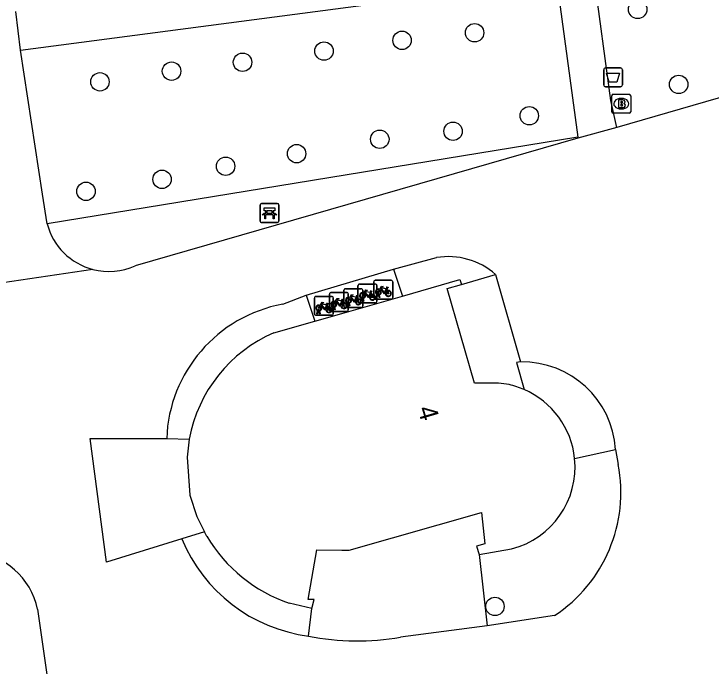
# Model space of a CAD drawing. Extents: x 162157 to 163165, y 378998 to 380775.
# Drawn here: x 162482.61 to 162519.6, y 379969 to 380003.63 of the extents above; entities that cross this region are included whole.
import ezdxf

# ---------------------------------------------------------------- set-up
doc = ezdxf.new("R2010")
doc.units = 0
for name, color, linetype in [('IMGEO_Afvalbak', 7, 'Continuous'), ('IMGEO_Bank', 7, 'Continuous'), ('IMGEO_Boom', 7, 'Continuous'), ('IMGEO_Brandkraan', 7, 'Continuous'), ('IMGEO_Fietsenrek', 7, 'Continuous'), ('IMGEO_Haag', 7, 'Continuous'), ('IMGEO_Loofbos', 7, 'Continuous'), ('IMGEO_Pand', 7, 'Continuous'), ('IMGEO_Pand_nummerreeks', 7, 'Continuous'), ('IMGEO_Parkeervlak_open', 7, 'Continuous'), ('IMGEO_Voetpad_halfverhard', 7, 'Continuous'), ('IMGEO_Voetpad_open', 7, 'Continuous')]:
    doc.layers.add(name, color=color, linetype=linetype)

msp = doc.modelspace()

# ---------------------------------------------------------------- linework, layer by layer
at = {"layer": 'IMGEO_Afvalbak'}
for p, q in [((162513.899, 379999.864), (162513.899, 380000.664)), ((162513.899, 380000.664), (162513.899, 379999.864)), ((162513.999, 380000.764), (162514.789, 380000.764)), ((162514.789, 380000.764), (162513.999, 380000.764)), ((162514.889, 380000.664), (162514.889, 379999.864)), ((162514.889, 379999.864), (162514.889, 380000.664)), ((162514.789, 379999.764), (162513.999, 379999.764)), ((162513.999, 379999.764), (162514.789, 379999.764))]:
    msp.add_line(p, q, dxfattribs=at)
msp.add_lwpolyline([(162514.042, 380000.478), (162514.746, 380000.478), (162514.597, 380000.008), (162514.191, 380000.008), (162514.042, 380000.478)], dxfattribs=at)
for centre, start, end in [((162513.999, 380000.664), 90, 180), ((162513.999, 380000.664), 90, 180), ((162514.789, 380000.664), 0, 90), ((162514.789, 380000.664), 360, 90), ((162513.999, 379999.864), 180, 270), ((162513.999, 379999.864), 180, 270), ((162514.789, 379999.864), 270, 0), ((162514.789, 379999.864), 270, 0)]:
    msp.add_arc(centre, 0.1, start, end, dxfattribs=at)
at = {"layer": 'IMGEO_Bank'}
for p, q in [((162495.666, 379992.631), (162495.666, 379993.472)), ((162495.666, 379993.472), (162495.666, 379992.631)), ((162495.741, 379993.556), (162496.582, 379993.556)), ((162496.582, 379993.556), (162495.741, 379993.556)), ((162496.666, 379993.481), (162496.666, 379992.64)), ((162496.666, 379992.64), (162496.666, 379993.481)), ((162495.975, 379993.062), (162495.975, 379993.168)), ((162496.019, 379993.168), (162496.019, 379993.062)), ((162496.307, 379993.174), (162496.025, 379993.174)), ((162496.025, 379993.056), (162496.307, 379993.056)), ((162496.313, 379993.062), (162496.313, 379993.168)), ((162496.357, 379993.168), (162496.357, 379993.062)), ((162496.363, 379992.954), (162495.97, 379992.954)), ((162496.591, 379992.556), (162495.75, 379992.556)), ((162495.75, 379992.556), (162496.591, 379992.556))]:
    msp.add_line(p, q, dxfattribs=at)
for points in [[(162495.913, 379992.954), (162495.771, 379992.954), (162495.883, 379993.056), (162495.969, 379993.056)], [(162495.969, 379993.174), (162495.883, 379993.174), (162495.883, 379993.335), (162496.446, 379993.335), (162496.446, 379993.174), (162496.363, 379993.174)], [(162496.363, 379993.056), (162496.446, 379993.056), (162496.558, 379992.954), (162496.419, 379992.954)], [(162495.963, 379992.947), (162495.963, 379992.74), (162495.92, 379992.74), (162495.92, 379992.947)], [(162496.413, 379992.947), (162496.413, 379992.74), (162496.369, 379992.74), (162496.369, 379992.947)]]:
    msp.add_lwpolyline(points, dxfattribs=at)
for centre, radius, start, end in [((162495.744, 379993.478), 0.0779, 92.4484, 184.2845), ((162495.744, 379993.478), 0.0779, 92.4484, 184.2845), ((162496.588, 379993.478), 0.0779, 2.4484, 94.2845), ((162496.588, 379993.478), 0.0779, 2.4484, 94.2845), ((162495.968, 379993.167), 0.00671, 2.8957, 87.1043), ((162495.968, 379993.063), 0.00671, 272.8957, 357.1043), ((162496.025, 379993.167), 0.00671, 92.8957, 177.1043), ((162496.025, 379993.063), 0.00671, 182.8957, 267.1043), ((162496.307, 379993.167), 0.00671, 2.8957, 87.1043), ((162496.307, 379993.063), 0.00671, 272.8957, 357.1043), ((162496.364, 379993.167), 0.00671, 92.8957, 177.1043), ((162496.364, 379993.063), 0.00671, 182.8957, 267.1043), ((162495.913, 379992.947), 0.00671, 2.8957, 87.1043), ((162495.97, 379992.947), 0.00671, 92.8957, 177.1043), ((162496.362, 379992.947), 0.00671, 2.8957, 87.1043), ((162496.419, 379992.947), 0.00671, 92.8957, 177.1043), ((162495.744, 379992.634), 0.0779, 182.4484, 274.2845), ((162495.744, 379992.634), 0.0779, 182.4484, 274.2845), ((162496.588, 379992.634), 0.0779, 272.4484, 4.2845), ((162496.588, 379992.634), 0.0779, 272.4484, 4.2845)]:
    msp.add_arc(centre, radius, start, end, dxfattribs=at)
at = {"layer": 'IMGEO_Boom'}
for centre in [(162515.703, 380003.867), (162507.049, 380002.628), (162503.203, 380002.225), (162499.06, 380001.655), (162494.737, 380001.06), (162490.971, 380000.589), (162487.172, 380000.022), (162517.876, 379999.885), (162509.952, 379998.224), (162505.906, 379997.397), (162502.021, 379996.973), (162497.606, 379996.207), (162493.841, 379995.54), (162490.467, 379994.844), (162486.433, 379994.208), (162508.129, 379972.166)]:
    msp.add_circle(centre, 0.489, dxfattribs=at)
at = {"layer": 'IMGEO_Brandkraan'}
for p, q in [((162514.408, 379999.361), (162515.26, 379999.361)), ((162514.333, 379998.435), (162514.333, 379999.287)), ((162514.821, 379999.141), (162514.846, 379999.141)), ((162515.334, 379999.287), (162515.334, 379998.435)), ((162514.844, 379998.581), (162514.819, 379998.581)), ((162515.26, 379998.361), (162514.408, 379998.361))]:
    msp.add_line(p, q, dxfattribs=at)
for points in [[(162514.408, 379999.361), (162515.26, 379999.361)], [(162514.333, 379998.435), (162514.333, 379999.287)], [(162514.681, 379999.061), (162514.681, 379998.661), (162514.894, 379998.661)], [(162514.912, 379999.061), (162514.681, 379999.061)], [(162514.86, 379998.98), (162514.806, 379998.98), (162514.806, 379998.904)], [(162515.334, 379999.287), (162515.334, 379998.435)], [(162514.806, 379998.904), (162514.859, 379998.904)], [(162514.868, 379998.828), (162514.806, 379998.828), (162514.806, 379998.747)], [(162514.806, 379998.747), (162514.868, 379998.747)], [(162515.26, 379998.361), (162514.408, 379998.361)]]:
    msp.add_lwpolyline(points, dxfattribs=at)
for centre, radius, start, end in [((162514.41, 379999.285), 0.0765, 91.552, 178.448), ((162514.41, 379999.285), 0.0765, 91.552, 178.448), ((162515.258, 379999.285), 0.0765, 1.552, 88.448), ((162515.258, 379999.285), 0.0765, 1.552, 88.448), ((162514.861, 379998.942), 0.0379, 267.8285, 90.9355), ((162514.916, 379998.916), 0.145, 59.4692, 91.5367), ((162514.941, 379998.963), 0.0922, 285.5137, 58.1501), ((162514.869, 379998.787), 0.0404, 269.8759, 90.5077), ((162514.9, 379998.912), 0.251, 268.6676, 293.5347), ((162514.946, 379998.771), 0.105, 301.3115, 78.989), ((162514.41, 379998.437), 0.0765, 181.552, 268.448), ((162514.41, 379998.437), 0.0765, 181.552, 268.448), ((162515.258, 379998.437), 0.0765, 271.552, 358.448), ((162515.258, 379998.437), 0.0765, 271.552, 358.448)]:
    msp.add_arc(centre, radius, start, end, dxfattribs=at)
for centre, major_axis, ratio, start_param, end_param in [((162514.82, 379998.861), (-0.387, 0.002), 0.722429, 4.712389, 7.853982), ((162514.845, 379998.861), (-0.39, 0.002), 0.717154, 1.570796, 4.712389)]:
    msp.add_ellipse(centre, major_axis=major_axis, ratio=ratio, start_param=start_param, end_param=end_param, dxfattribs=at)
at = {"layer": 'IMGEO_Fietsenrek'}
for p, q in [((162501.708, 379988.559), (162501.708, 379989.4)), ((162501.708, 379989.4), (162501.708, 379988.559)), ((162501.783, 379989.484), (162502.624, 379989.484)), ((162502.624, 379989.484), (162501.783, 379989.484)), ((162502.708, 379989.409), (162502.708, 379988.568)), ((162502.708, 379988.568), (162502.708, 379989.409)), ((162500.193, 379989.038), (162501.034, 379989.038)), ((162501.034, 379989.038), (162500.193, 379989.038)), ((162500.864, 379988.358), (162500.864, 379989.199)), ((162500.864, 379989.199), (162500.864, 379988.358)), ((162500.939, 379989.283), (162501.78, 379989.283)), ((162501.78, 379989.283), (162500.939, 379989.283)), ((162501.118, 379988.963), (162501.118, 379988.122)), ((162501.118, 379988.122), (162501.118, 379988.963)), ((162501.864, 379989.208), (162501.864, 379988.367)), ((162501.864, 379988.367), (162501.864, 379989.208)), ((162502.395, 379989.033), (162502.431, 379988.938)), ((162498.623, 379988.625), (162499.464, 379988.625)), ((162499.464, 379988.625), (162498.623, 379988.625)), ((162499.348, 379987.909), (162499.348, 379988.75)), ((162499.348, 379988.75), (162499.348, 379987.909)), ((162499.423, 379988.834), (162500.264, 379988.834)), ((162500.264, 379988.834), (162499.423, 379988.834)), ((162500.118, 379988.113), (162500.118, 379988.954)), ((162500.118, 379988.954), (162500.118, 379988.113)), ((162500.348, 379988.759), (162500.348, 379987.918)), ((162500.348, 379987.918), (162500.348, 379988.759)), ((162501.551, 379988.832), (162501.587, 379988.737)), ((162501.835, 379988.568), (162501.874, 379988.728)), ((162501.904, 379988.716), (162501.869, 379988.568)), ((162501.946, 379988.74), (162501.945, 379988.744)), ((162501.987, 379988.568), (162501.953, 379988.71)), ((162501.977, 379988.751), (162501.978, 379988.744)), ((162501.985, 379988.714), (162502.02, 379988.568)), ((162498.548, 379987.7), (162498.548, 379988.541)), ((162498.548, 379988.541), (162498.548, 379987.7)), ((162499.548, 379988.55), (162499.548, 379987.709)), ((162499.548, 379987.709), (162499.548, 379988.55)), ((162500.035, 379988.383), (162500.071, 379988.288)), ((162500.245, 379988.122), (162500.284, 379988.282)), ((162500.314, 379988.27), (162500.279, 379988.122)), ((162500.356, 379988.294), (162500.355, 379988.298)), ((162500.397, 379988.122), (162500.363, 379988.264)), ((162500.387, 379988.305), (162500.388, 379988.298)), ((162500.395, 379988.268), (162500.43, 379988.122)), ((162500.805, 379988.587), (162500.841, 379988.492)), ((162501.789, 379988.283), (162500.948, 379988.283)), ((162500.948, 379988.283), (162501.789, 379988.283)), ((162500.991, 379988.367), (162501.03, 379988.527)), ((162501.025, 379988.367), (162500.991, 379988.367)), ((162501.06, 379988.515), (162501.025, 379988.367)), ((162501.102, 379988.539), (162501.101, 379988.543)), ((162501.143, 379988.367), (162501.109, 379988.509)), ((162501.133, 379988.55), (162501.134, 379988.543)), ((162501.141, 379988.513), (162501.176, 379988.367)), ((162501.176, 379988.367), (162501.143, 379988.367)), ((162502.633, 379988.484), (162501.792, 379988.484)), ((162501.792, 379988.484), (162502.633, 379988.484)), ((162501.869, 379988.568), (162501.835, 379988.568)), ((162502.02, 379988.568), (162501.987, 379988.568)), ((162498.675, 379987.709), (162498.714, 379987.869)), ((162498.744, 379987.857), (162498.709, 379987.709)), ((162498.786, 379987.881), (162498.785, 379987.885)), ((162498.817, 379987.892), (162498.818, 379987.885)), ((162498.825, 379987.855), (162498.86, 379987.709)), ((162499.235, 379988.174), (162499.271, 379988.079)), ((162499.475, 379987.918), (162499.514, 379988.078)), ((162499.509, 379987.918), (162499.475, 379987.918)), ((162499.544, 379988.066), (162499.509, 379987.918)), ((162499.586, 379988.09), (162499.585, 379988.094)), ((162499.627, 379987.918), (162499.593, 379988.06)), ((162499.617, 379988.101), (162499.618, 379988.094)), ((162499.625, 379988.064), (162499.66, 379987.918)), ((162499.66, 379987.918), (162499.627, 379987.918)), ((162501.043, 379988.038), (162500.202, 379988.038)), ((162500.202, 379988.038), (162501.043, 379988.038)), ((162500.279, 379988.122), (162500.245, 379988.122)), ((162500.43, 379988.122), (162500.397, 379988.122)), ((162499.473, 379987.625), (162498.632, 379987.625)), ((162498.632, 379987.625), (162499.473, 379987.625)), ((162498.709, 379987.709), (162498.675, 379987.709)), ((162498.827, 379987.709), (162498.793, 379987.851)), ((162498.86, 379987.709), (162498.827, 379987.709)), ((162500.273, 379987.834), (162499.432, 379987.834)), ((162499.432, 379987.834), (162500.273, 379987.834))]:
    msp.add_line(p, q, dxfattribs=at)
for points in [[(162501.177, 379988.809), (162501.272, 379988.973), (162501.358, 379988.959), (162501.36, 379988.95), (162501.304, 379988.939), (162501.277, 379988.894), (162501.533, 379988.853)], [(162502.042, 379988.958), (162501.99, 379988.868), (162501.95, 379988.843), (162501.951, 379988.89), (162502.006, 379988.984)], [(162502.021, 379989.01), (162502.116, 379989.174), (162502.202, 379989.16), (162502.204, 379989.151), (162502.148, 379989.14), (162502.121, 379989.095), (162502.377, 379989.054)], [(162502.317, 379988.766), (162502.267, 379988.766), (162502.076, 379989.017), (162502.057, 379988.985)], [(162502.364, 379989.029), (162502.107, 379989.07), (162502.09, 379989.041), (162502.257, 379988.821), (162502.364, 379989.029)], [(162502.412, 379988.931), (162502.382, 379989.008), (162502.273, 379988.79), (162502.316, 379988.79)], [(162502.377, 379989.054), (162502.402, 379989.103), (162502.396, 379989.107), (162502.373, 379989.111), (162502.361, 379989.118), (162502.36, 379989.121), (162502.362, 379989.126), (162502.457, 379989.111), (162502.459, 379989.101), (162502.449, 379989.088), (162502.437, 379989.082), (162502.423, 379989.088), (162502.395, 379989.033)], [(162500.431, 379988.564), (162500.526, 379988.728), (162500.612, 379988.714), (162500.614, 379988.705), (162500.558, 379988.694), (162500.531, 379988.649), (162500.787, 379988.608)], [(162500.774, 379988.583), (162500.517, 379988.624), (162500.5, 379988.595), (162500.667, 379988.375), (162500.774, 379988.583)], [(162500.787, 379988.608), (162500.812, 379988.657), (162500.806, 379988.661), (162500.783, 379988.665), (162500.771, 379988.672), (162500.77, 379988.675), (162500.772, 379988.68), (162500.867, 379988.665), (162500.869, 379988.655), (162500.859, 379988.642), (162500.847, 379988.636), (162500.833, 379988.642), (162500.805, 379988.587)], [(162501.198, 379988.757), (162501.146, 379988.667), (162501.106, 379988.642), (162501.107, 379988.689), (162501.162, 379988.783)], [(162501.473, 379988.565), (162501.423, 379988.565), (162501.232, 379988.816), (162501.213, 379988.784)], [(162501.52, 379988.828), (162501.263, 379988.869), (162501.246, 379988.84), (162501.413, 379988.62), (162501.52, 379988.828)], [(162501.568, 379988.73), (162501.538, 379988.807), (162501.429, 379988.589), (162501.472, 379988.589)], [(162501.502, 379988.589), (162501.622, 379988.588), (162501.578, 379988.702)], [(162501.598, 379988.709), (162501.653, 379988.564), (162501.503, 379988.564)], [(162501.533, 379988.853), (162501.558, 379988.902), (162501.552, 379988.906), (162501.529, 379988.91), (162501.517, 379988.917), (162501.516, 379988.92), (162501.518, 379988.925), (162501.613, 379988.91), (162501.615, 379988.9), (162501.605, 379988.887), (162501.593, 379988.881), (162501.579, 379988.887), (162501.551, 379988.832)], [(162502.346, 379988.79), (162502.466, 379988.789), (162502.422, 379988.903)], [(162502.442, 379988.91), (162502.497, 379988.765), (162502.347, 379988.765)], [(162498.861, 379988.151), (162498.956, 379988.315), (162499.042, 379988.301), (162499.044, 379988.292), (162498.988, 379988.281), (162498.961, 379988.236), (162499.217, 379988.195)], [(162499.217, 379988.195), (162499.242, 379988.244), (162499.236, 379988.248), (162499.213, 379988.252), (162499.201, 379988.259), (162499.2, 379988.262), (162499.202, 379988.267), (162499.297, 379988.252), (162499.299, 379988.242), (162499.289, 379988.229), (162499.277, 379988.223), (162499.263, 379988.229), (162499.235, 379988.174)], [(162499.682, 379988.308), (162499.63, 379988.218), (162499.59, 379988.193), (162499.591, 379988.24), (162499.646, 379988.334)], [(162499.661, 379988.36), (162499.756, 379988.524), (162499.842, 379988.51), (162499.844, 379988.501), (162499.788, 379988.49), (162499.761, 379988.445), (162500.017, 379988.404)], [(162499.957, 379988.116), (162499.907, 379988.116), (162499.716, 379988.367), (162499.697, 379988.335)], [(162500.004, 379988.379), (162499.747, 379988.42), (162499.73, 379988.391), (162499.897, 379988.171), (162500.004, 379988.379)], [(162500.052, 379988.281), (162500.022, 379988.358), (162499.913, 379988.14), (162499.956, 379988.14)], [(162499.986, 379988.14), (162500.106, 379988.139), (162500.062, 379988.253)], [(162500.082, 379988.26), (162500.137, 379988.115), (162499.987, 379988.115)], [(162500.017, 379988.404), (162500.042, 379988.453), (162500.036, 379988.457), (162500.013, 379988.461), (162500.001, 379988.468), (162500, 379988.471), (162500.002, 379988.476), (162500.097, 379988.461), (162500.099, 379988.451), (162500.089, 379988.438), (162500.077, 379988.432), (162500.063, 379988.438), (162500.035, 379988.383)], [(162500.452, 379988.512), (162500.4, 379988.422), (162500.36, 379988.397), (162500.361, 379988.444), (162500.416, 379988.538)], [(162500.727, 379988.32), (162500.677, 379988.32), (162500.486, 379988.571), (162500.467, 379988.539)], [(162500.822, 379988.485), (162500.792, 379988.562), (162500.683, 379988.344), (162500.726, 379988.344)], [(162500.756, 379988.344), (162500.876, 379988.343), (162500.832, 379988.457)], [(162500.852, 379988.464), (162500.907, 379988.319), (162500.757, 379988.319)], [(162498.882, 379988.099), (162498.83, 379988.009), (162498.79, 379987.984), (162498.791, 379988.031), (162498.846, 379988.125)], [(162499.157, 379987.907), (162499.107, 379987.907), (162498.916, 379988.158), (162498.897, 379988.126)], [(162499.204, 379988.17), (162498.947, 379988.211), (162498.93, 379988.182), (162499.097, 379987.962), (162499.204, 379988.17)], [(162499.252, 379988.072), (162499.222, 379988.149), (162499.113, 379987.931), (162499.156, 379987.931)], [(162499.186, 379987.931), (162499.306, 379987.93), (162499.262, 379988.044)], [(162499.282, 379988.051), (162499.337, 379987.906), (162499.187, 379987.906)]]:
    msp.add_lwpolyline(points, dxfattribs=at)
for centre, radius, start, end in [((162501.786, 379989.406), 0.0779, 92.4484, 184.2845), ((162501.786, 379989.406), 0.0779, 92.4484, 184.2845), ((162502.63, 379989.406), 0.0779, 2.4484, 94.2845), ((162502.63, 379989.406), 0.0779, 2.4484, 94.2845), ((162500.196, 379988.96), 0.0779, 92.4484, 184.2845), ((162500.196, 379988.96), 0.0779, 92.4484, 184.2845), ((162500.942, 379989.205), 0.0779, 92.4484, 184.2845), ((162500.942, 379989.205), 0.0779, 92.4484, 184.2845), ((162501.04, 379988.96), 0.0779, 2.4484, 94.2845), ((162501.04, 379988.96), 0.0779, 2.4484, 94.2845), ((162501.786, 379989.205), 0.0779, 2.4484, 94.2845), ((162501.786, 379989.205), 0.0779, 2.4484, 94.2845), ((162501.948, 379988.869), 0.159, 62.6766, 242.1369), ((162501.948, 379988.869), 0.129, 63.3192, 238.903), ((162501.948, 379988.869), 0.159, 283.5766, 46.6042), ((162498.626, 379988.547), 0.0779, 92.4484, 184.2845), ((162498.626, 379988.547), 0.0779, 92.4484, 184.2845), ((162499.426, 379988.756), 0.0779, 92.4484, 184.2845), ((162499.426, 379988.756), 0.0779, 92.4484, 184.2845), ((162499.47, 379988.547), 0.0779, 2.4484, 94.2845), ((162499.47, 379988.547), 0.0779, 2.4484, 94.2845), ((162500.27, 379988.756), 0.0779, 2.4484, 94.2845), ((162500.27, 379988.756), 0.0779, 2.4484, 94.2845), ((162501.104, 379988.668), 0.159, 62.6766, 242.1369), ((162501.104, 379988.668), 0.129, 63.3192, 238.903), ((162501.104, 379988.668), 0.129, 283.6043, 43.4302), ((162501.104, 379988.668), 0.159, 283.5766, 46.6042), ((162501.631, 379988.584), 0.159, 113.3408, 178.3217), ((162501.631, 379988.584), 0.159, 187.0065, 105.7708), ((162501.631, 379988.584), 0.129, 113.923, 177.9556), ((162501.631, 379988.584), 0.129, 188.6715, 104.5883), ((162501.928, 379988.74), 0.0499, 12.8025, 158.6934), ((162501.948, 379988.869), 0.159, 253.9967, 271.7867), ((162501.928, 379988.74), 0.0174, 12.8025, 163.4502), ((162501.948, 379988.869), 0.129, 253.415, 269.0204), ((162501.948, 379988.869), 0.129, 283.6043, 43.4302), ((162502.475, 379988.785), 0.159, 113.3408, 178.3217), ((162502.475, 379988.785), 0.159, 187.0065, 105.7708), ((162502.475, 379988.785), 0.129, 113.923, 177.9556), ((162502.475, 379988.785), 0.129, 188.6715, 104.5883), ((162499.588, 379988.219), 0.159, 62.6766, 242.1369), ((162499.588, 379988.219), 0.129, 63.3192, 238.903), ((162499.588, 379988.219), 0.129, 283.6043, 43.4302), ((162499.588, 379988.219), 0.159, 283.5766, 46.6042), ((162500.115, 379988.135), 0.159, 113.3408, 178.3217), ((162500.115, 379988.135), 0.159, 187.0065, 105.7708), ((162500.115, 379988.135), 0.129, 113.923, 177.9556), ((162500.115, 379988.135), 0.129, 188.6715, 104.5883), ((162500.358, 379988.423), 0.159, 62.6766, 242.1369), ((162500.358, 379988.423), 0.129, 63.3192, 238.903), ((162500.338, 379988.294), 0.0499, 12.8025, 158.6934), ((162500.358, 379988.423), 0.159, 253.9967, 271.7867), ((162500.338, 379988.294), 0.0174, 12.8025, 163.4502), ((162500.358, 379988.423), 0.129, 253.415, 269.0204), ((162500.358, 379988.423), 0.129, 283.6043, 43.4302), ((162500.358, 379988.423), 0.159, 283.5766, 46.6042), ((162500.885, 379988.339), 0.159, 113.3408, 178.3217), ((162500.885, 379988.339), 0.159, 187.0065, 105.7708), ((162500.885, 379988.339), 0.129, 113.923, 177.9556), ((162500.885, 379988.339), 0.129, 188.6715, 104.5883), ((162500.942, 379988.361), 0.0779, 182.4484, 274.2845), ((162500.942, 379988.361), 0.0779, 182.4484, 274.2845), ((162501.084, 379988.539), 0.0499, 12.8025, 158.6934), ((162501.104, 379988.668), 0.159, 253.9967, 271.7867), ((162501.084, 379988.539), 0.0174, 12.8025, 163.4502), ((162501.104, 379988.668), 0.129, 253.415, 269.0204), ((162501.786, 379988.562), 0.0779, 182.4484, 274.2845), ((162501.786, 379988.562), 0.0779, 182.4484, 274.2845), ((162501.786, 379988.361), 0.0779, 272.4484, 4.2845), ((162501.786, 379988.361), 0.0779, 272.4484, 4.2845), ((162502.63, 379988.562), 0.0779, 272.4484, 4.2845), ((162502.63, 379988.562), 0.0779, 272.4484, 4.2845), ((162498.788, 379988.01), 0.159, 62.6766, 242.1369), ((162498.788, 379988.01), 0.129, 63.3192, 238.903), ((162498.768, 379987.881), 0.0499, 12.8025, 158.6934), ((162498.788, 379988.01), 0.159, 253.9967, 271.7867), ((162498.768, 379987.881), 0.0174, 12.8025, 163.4502), ((162498.788, 379988.01), 0.129, 253.415, 269.0204), ((162498.788, 379988.01), 0.129, 283.6043, 43.4302), ((162498.788, 379988.01), 0.159, 283.5766, 46.6042), ((162499.315, 379987.926), 0.159, 113.3408, 178.3217), ((162499.315, 379987.926), 0.159, 187.0065, 105.7708), ((162499.315, 379987.926), 0.129, 113.923, 177.9556), ((162499.315, 379987.926), 0.129, 188.6715, 104.5883), ((162499.426, 379987.912), 0.0779, 182.4484, 274.2845), ((162499.426, 379987.912), 0.0779, 182.4484, 274.2845), ((162499.568, 379988.09), 0.0499, 12.8025, 158.6934), ((162499.588, 379988.219), 0.159, 253.9967, 271.7867), ((162499.568, 379988.09), 0.0174, 12.8025, 163.4502), ((162499.588, 379988.219), 0.129, 253.415, 269.0204), ((162500.196, 379988.116), 0.0779, 182.4484, 274.2845), ((162500.196, 379988.116), 0.0779, 182.4484, 274.2845), ((162500.27, 379987.912), 0.0779, 272.4484, 4.2845), ((162500.27, 379987.912), 0.0779, 272.4484, 4.2845), ((162501.04, 379988.116), 0.0779, 272.4484, 4.2845), ((162501.04, 379988.116), 0.0779, 272.4484, 4.2845), ((162498.626, 379987.703), 0.0779, 182.4484, 274.2845), ((162498.626, 379987.703), 0.0779, 182.4484, 274.2845), ((162499.47, 379987.703), 0.0779, 272.4484, 4.2845), ((162499.47, 379987.703), 0.0779, 272.4484, 4.2845)]:
    msp.add_arc(centre, radius, start, end, dxfattribs=at)
at = {"layer": 'IMGEO_Haag'}
msp.add_lwpolyline([(162512.356, 379980.024), (162514.524, 379980.502)], dxfattribs=at)
at = {"layer": 'IMGEO_Loofbos'}
msp.add_lwpolyline([(162512.519, 379997.087), (162484.373, 379992.484)], dxfattribs=at)
at = {"layer": 'IMGEO_Pand'}
for points in [[(162503.217, 379988.648), (162506.275, 379989.522), (162506.35, 379989.262)], [(162508.885, 379983.942), (162508.319, 379984.028), (162507.038, 379984.028), (162505.591, 379989.043), (162506.35, 379989.262)], [(162498.576, 379987.322), (162500, 379987.729), (162503.217, 379988.648)], [(162496.405, 379986.702), (162498.576, 379987.322)], [(162491.914, 379981.055), (162491.797, 379980.085), (162491.948, 379978.081), (162492.319, 379976.948), (162492.728, 379976.129)], [(162498.418, 379972.056), (162498.538, 379972.536), (162498.218, 379972.536), (162498.68, 379975.175), (162500, 379975.16), (162500.397, 379975.155), (162507.421, 379977.162), (162507.599, 379975.498), (162507.158, 379975.372), (162507.286, 379974.922)], [(162492.848, 379975.888), (162492.728, 379976.129)], [(162507.286, 379974.922), (162509.015, 379975.222)], [(162498.418, 379972.056), (162497.219, 379972.337)]]:
    msp.add_lwpolyline(points, dxfattribs=at)
for centre, radius, start, end in [((162499.474, 379979.652), 7.689, 113.5231, 169.4871), ((162507.87, 379979.497), 4.56, 66.6852, 77.1425), ((162507.895, 379979.568), 4.484, 5.8309, 66.6157), ((162507.891, 379979.567), 4.488, 284.5013, 5.842), ((162499.856, 379980.049), 8.15, 210.6975, 251.1217)]:
    msp.add_arc(centre, radius, start, end, dxfattribs=at)
at = {"layer": 'IMGEO_Parkeervlak_open'}
for points in [[(162507.286, 379974.922), (162507.711, 379971.131)], [(162498.238, 379970.588), (162498.418, 379972.056)]]:
    msp.add_lwpolyline(points, dxfattribs=at)
at = {"layer": 'IMGEO_Voetpad_halfverhard'}
for points in [[(162514.588, 379997.596), (162514.279, 379999.035), (162513.384, 380005.741), (162549.199, 380010.452)], [(162482.966, 380001.698), (162511.388, 380005.454), (162512.519, 379997.087)], [(162512.527, 379997.031), (162512.519, 379997.087)]]:
    msp.add_lwpolyline(points, dxfattribs=at)
at = {"layer": 'IMGEO_Voetpad_open'}
for points in [[(162547.53, 380007.164), (162514.588, 379997.596)], [(162482.966, 380001.698), (162482.713, 380003.762)], [(162484.373, 379992.484), (162484.133, 379994.059), (162482.966, 380001.698)], [(162514.588, 379997.596), (162512.527, 379997.031)], [(162512.527, 379997.031), (162489.042, 379990.254)], [(162502.74, 379990.077), (162505.035, 379990.689)], [(162498.109, 379988.686), (162502.74, 379990.077)], [(162502.74, 379990.077), (162503.217, 379988.648)], [(162486.798, 379990.062), (162481.519, 379989.275)], [(162506.35, 379989.262), (162508.155, 379989.798)], [(162508.155, 379989.798), (162509.487, 379985.152)], [(162496.868, 379988.217), (162498.109, 379988.686)], [(162498.109, 379988.686), (162498.576, 379987.322)], [(162509.487, 379985.152), (162509.275, 379985.113), (162509.675, 379983.684)], [(162491.513, 379975.749), (162487.52, 379974.511), (162486.653, 379981.085), (162490.714, 379981.076)], [(162490.714, 379981.076), (162491.914, 379981.055)], [(162514.524, 379980.502), (162514.675, 379979.706)], [(162492.728, 379976.129), (162491.513, 379975.749)], [(162483.859, 379972.022), (162485.015, 379963.949), (162514.096, 379967.843)], [(162511.292, 379971.682), (162507.711, 379971.131)], [(162507.711, 379971.131), (162503.124, 379970.536)]]:
    msp.add_lwpolyline(points, dxfattribs=at)
for centre, radius, start, end in [((162487.648, 379993.338), 3.385, 194.6182, 255.4527), ((162505.657, 379986.959), 3.781, 48.6556, 99.4682), ((162487.648, 379993.341), 3.387, 255.4729, 294.3079), ((162498.24, 379980.813), 7.53, 100.496, 177.9955), ((162509.58, 379980.199), 4.953, 3.5018, 91.0737), ((162506.967, 379978.231), 7.848, 303.4432, 10.8353), ((162499.347, 379978.995), 8.479, 202.5049, 262.4873), ((162480.092, 379971.233), 3.849, 11.8326, 85.219), ((162500.817, 379983.367), 13.037, 258.5892, 280.1913)]:
    msp.add_arc(centre, radius, start, end, dxfattribs=at)

# ---------------------------------------------------------------- texts
at = {"layer": 'IMGEO_Pand_nummerreeks'}
msp.add_text('4', height=1, rotation=286.0942, dxfattribs=at).set_placement((162504.017, 379982.668))

doc.saveas('drawing.dxf')
